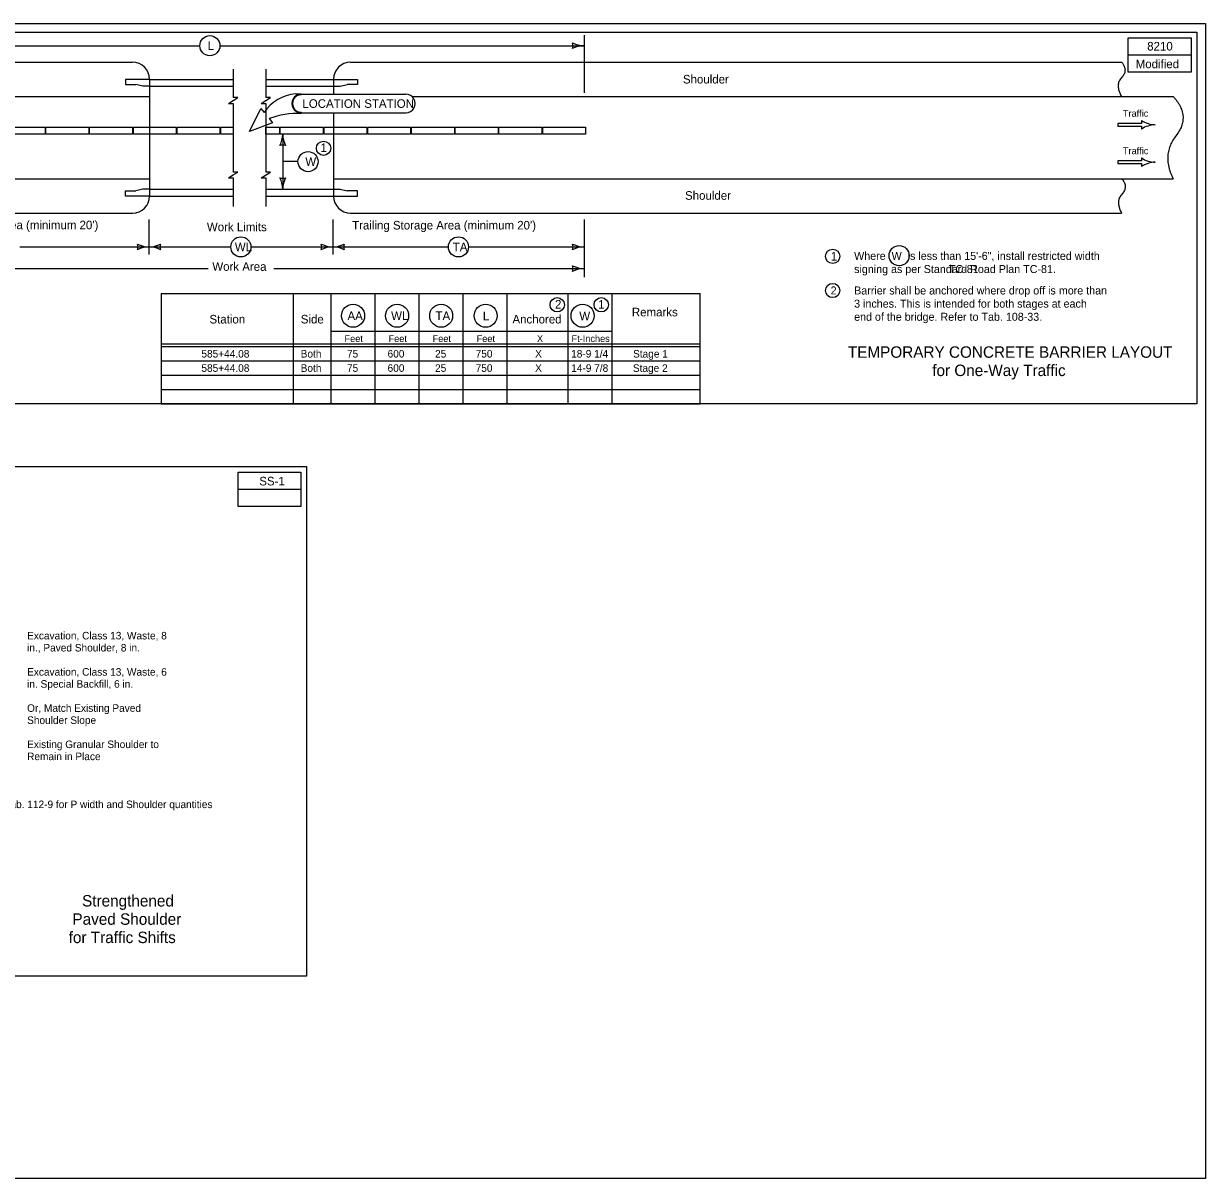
# Model space of a CAD drawing. Extents: x 8045 to 81668, y 6217 to 16762.
# Drawn here: x 14801 to 16868, y 7924 to 9944 of the extents above; entities that cross this region are included whole.
import ezdxf

# ---------------------------------------------------------------- set-up
doc = ezdxf.new("R2010")
doc.units = 0
for name, color, linetype in [('dsnNonPlotable', 7, 'Continuous'), ('dsnShtPlotShapeBatchPrint', 7, 'Continuous'), ('dsnStdBlockModified', 7, 'Continuous'), ('dsnStdBlockNotModified', 7, 'Continuous'), ('dsnStdBorder', 7, 'Continuous'), ('dsnStdLineWork', 7, 'Continuous'), ('dsnStdNameDate', 7, 'Continuous'), ('dsnStdSection', 7, 'Continuous'), ('Level 2', 7, 'Continuous'), ('Level 3', 7, 'Continuous'), ('Level 5', 7, 'Continuous')]:
    doc.layers.add(name, color=color, linetype=linetype)

msp = doc.modelspace()

# ---------------------------------------------------------------- linework, layer by layer
at = {"layer": 'dsnNonPlotable'}
for p, q in [((15781, 9924.1), (15781, 9823.2)), ((14230.5, 9905.4), (15109, 9905.4)), ((15144.3, 9905.4), (15781, 9905.4)), ((13862.8, 9876.4), (14991.3, 9876.4)), ((15167.3, 9864.4), (15167.3, 9814.6)), ((15224.4, 9864.4), (15224.4, 9814.6)), ((15372.7, 9876.4), (16721.1, 9876.4)), ((15021.3, 9846.4), (14979.3, 9846.4)), ((14979.3, 9846.4), (14979.3, 9837.4)), ((14979.3, 9837.4), (14997.3, 9837.4)), ((15009.3, 9834.4), (14997.3, 9837.4)), ((15021.3, 9846.4), (15021.3, 9642.4)), ((15021.3, 9846.4), (15167.3, 9846.4)), ((15224.4, 9846.4), (15342.7, 9846.4)), ((15342.7, 9846.4), (15384.7, 9846.4)), ((15342.7, 9846.4), (15342.7, 9820.5)), ((15354.7, 9834.4), (15366.7, 9837.4)), ((15384.7, 9837.4), (15366.7, 9837.4)), ((15384.7, 9846.4), (15384.7, 9837.4)), ((13779.2, 9816.4), (15021.3, 9816.4)), ((15021.3, 9834.4), (15009.3, 9834.4)), ((15021.3, 9834.4), (15167.3, 9834.4)), ((15224.4, 9834.4), (15342.7, 9834.4)), ((15276.8, 9821), (15286.3, 9821.4)), ((15286.3, 9821.4), (15286.3, 9819.6)), ((15286.3, 9820.5), (15469.4, 9820.5)), ((15342.7, 9834.4), (15354.7, 9834.4)), ((15480.2, 9816.4), (16811.5, 9816.4)), ((15159.3, 9804.5), (15167.3, 9809.5)), ((15159.3, 9804.5), (15167.3, 9804.5)), ((15167.3, 9809.5), (15175.3, 9814.6)), ((15175.3, 9814.6), (15167.3, 9814.6)), ((15167.3, 9804.5), (15167.3, 9744.4)), ((15216.4, 9804.5), (15232.4, 9814.6)), ((15216.4, 9804.5), (15224.4, 9804.5)), ((15232.4, 9814.6), (15224.4, 9814.6)), ((15224.4, 9804.5), (15224.4, 9744.4)), ((15195.9, 9755.5), (15216, 9795.5)), ((15216, 9795.5), (15221.6, 9788.4)), ((15230.2, 9777.8), (15236.1, 9770.5)), ((15286.3, 9788.9), (15286.3, 9787.1)), ((15286.3, 9788), (15469.4, 9788)), ((15342.7, 9788), (15342.7, 9642.4)), ((15236.1, 9770.5), (15195.9, 9755.5)), ((16755.8, 9769.3), (16714.6, 9769.3)), ((16714.6, 9769.3), (16714.6, 9764.8)), ((16714.6, 9764.8), (16755.8, 9764.8)), ((16755.8, 9774.5), (16755.8, 9769.3)), ((16755.8, 9764.8), (16755.8, 9759.5)), ((16779.8, 9767), (16779.8, 9767)), ((15167.3, 9744.4), (15167.3, 9684.4)), ((15224.4, 9744.4), (15224.4, 9684.4)), ((15254, 9750.7), (15254, 9654.4)), ((15280.6, 9702.6), (15254, 9702.6)), ((16755.8, 9703.8), (16714.6, 9703.8)), ((16714.6, 9703.8), (16714.6, 9699.3)), ((16714.6, 9699.3), (16755.8, 9699.3)), ((16755.8, 9709.1), (16755.8, 9703.8)), ((16755.8, 9699.3), (16755.8, 9694.1)), ((16779.8, 9701.6), (16779.8, 9701.6)), ((13779.2, 9672.4), (15021.3, 9672.4)), ((15159.3, 9674.3), (15167.3, 9679.3)), ((15159.3, 9674.3), (15167.3, 9674.3)), ((15167.3, 9679.3), (15175.3, 9684.4)), ((15175.3, 9684.4), (15167.3, 9684.4)), ((15167.3, 9674.3), (15167.3, 9624.4)), ((15216.4, 9674.3), (15232.4, 9684.4)), ((15216.4, 9674.3), (15224.4, 9674.3)), ((15232.4, 9684.4), (15224.4, 9684.4)), ((15224.4, 9674.3), (15224.4, 9624.4)), ((15342.7, 9672.4), (16811.5, 9672.4)), ((14979.3, 9651.4), (14997.3, 9651.4)), ((14979.3, 9642.4), (14979.3, 9651.4)), ((15009.3, 9654.4), (14997.3, 9651.4)), ((15021.3, 9654.4), (15009.3, 9654.4)), ((15021.3, 9654.4), (15167.3, 9654.4)), ((15224.4, 9654.4), (15342.7, 9654.4)), ((15342.7, 9654.4), (15354.7, 9654.4)), ((15354.7, 9654.4), (15366.7, 9651.4)), ((15384.7, 9651.4), (15366.7, 9651.4)), ((15384.7, 9642.4), (15384.7, 9651.4)), ((15021.3, 9642.4), (14979.3, 9642.4)), ((15021.3, 9642.4), (15167.3, 9642.4)), ((15224.4, 9642.4), (15342.7, 9642.4)), ((15342.7, 9642.4), (15384.7, 9642.4)), ((13862.8, 9612.4), (14991.3, 9612.4)), ((15372.7, 9612.4), (16721.1, 9612.4)), ((15020.1, 9601.2), (15020.1, 9539.9)), ((15341.5, 9601.2), (15341.5, 9539.9)), ((15781, 9601.2), (15781, 9500.3)), ((14794, 9553.4), (15020.1, 9553.4)), ((15020.1, 9553.4), (15163.3, 9553.4)), ((15198.3, 9553.4), (15341.5, 9553.4)), ((15211, 9553.4), (15341.5, 9553.4)), ((15341.5, 9553.4), (15543.6, 9553.4)), ((15578.9, 9553.4), (15781, 9553.4)), ((14532.6, 9515.5), (15123.4, 9515.5)), ((15238.7, 9515.5), (15781, 9515.5)), ((15240.1, 9515.5), (15341.5, 9515.5)), ((15272.6, 9279), (15272.6, 9472)), ((15338.6, 9279), (15338.6, 9472)), ((15415.6, 9279), (15415.6, 9472)), ((15492.6, 9279), (15492.6, 9472)), ((15569.6, 9279), (15569.6, 9472)), ((15338.6, 9406.2), (15830.1, 9406.2)), ((15041.6, 9384), (15984.1, 9384)), ((15041.6, 9379), (15984.1, 9379))]:
    msp.add_line(p, q, dxfattribs=at)
for points in [[(14763.3, 9762.7), (14838.3, 9762.7), (14838.3, 9750.7), (14763.3, 9750.7)], [(14839.8, 9762.7), (14914.8, 9762.7), (14914.8, 9750.7), (14839.8, 9750.7)], [(14916.3, 9762.7), (14991.3, 9762.7), (14991.3, 9750.7), (14916.3, 9750.7)], [(14992.8, 9762.7), (15067.8, 9762.7), (15067.8, 9750.7), (14992.8, 9750.7)], [(15069.3, 9762.7), (15144.3, 9762.7), (15144.3, 9750.7), (15069.3, 9750.7)], [(15249.7, 9762.7), (15324.7, 9762.7), (15324.7, 9750.7), (15249.7, 9750.7)], [(15326.2, 9762.7), (15401.2, 9762.7), (15401.2, 9750.7), (15326.2, 9750.7)], [(15402.7, 9762.7), (15477.7, 9762.7), (15477.7, 9750.7), (15402.7, 9750.7)], [(15479.2, 9762.7), (15554.2, 9762.7), (15554.2, 9750.7), (15479.2, 9750.7)], [(15555.7, 9762.7), (15630.7, 9762.7), (15630.7, 9750.7), (15555.7, 9750.7)], [(15632.2, 9762.7), (15707.2, 9762.7), (15707.2, 9750.7), (15632.2, 9750.7)], [(15708.7, 9762.7), (15783.7, 9762.7), (15783.7, 9750.7), (15708.7, 9750.7)]]:
    msp.add_lwpolyline(points, close=True, dxfattribs=at)
for points in [[(15167.3, 9750.7), (15145.8, 9750.7), (15145.8, 9762.7), (15167.3, 9762.7)], [(15167.3, 9762.7), (15167.3, 9750.7)], [(15224.4, 9750.7), (15224.4, 9762.7)], [(15224.4, 9762.7), (15248.2, 9762.7), (15248.2, 9750.7), (15224.4, 9750.7)]]:
    msp.add_lwpolyline(points, dxfattribs=at)
for centre, radius in [((15126.6, 9905.4), 17.6), ((15325.4, 9726), 12.5), ((15298.3, 9702.6), 17.6), ((15180.8, 9553.4), 17.6), ((15561.3, 9553.4), 17.6), ((16215.8, 9537), 12.5), ((16215.8, 9537), 12.5), ((16331.9, 9538.1), 17.6), ((16331.9, 9538.1), 17.6), ((15377.1, 9433), 20.1), ((15454.1, 9433), 20.1), ((15531.1, 9433), 20.1), ((15608.9, 9433), 20.1), ((15734, 9452.2), 12.5), ((15778.4, 9433), 20.1), ((15811, 9452.2), 12.5)]:
    msp.add_circle(centre, radius, dxfattribs=at)
for centre, radius, start, end in [((15745.4, 9905.4), 16.4, 342.2666, 17.7333), ((15781, 9947.9), 42.5, 241.9275, 270), ((15781, 9862.9), 42.5, 90, 118.0725), ((14991.3, 9846.4), 30, 0, 90), ((15372.7, 9846.4), 30, 90, 180), ((16781.7, 9815.4), 48.4, 237.618, 267.648), ((16781.7, 9718.7), 48.4, 92.352, 122.382), ((15211.5, 9750.7), 42.5, 331.9275, 0), ((15296.5, 9750.7), 42.5, 180, 208.0725), ((15254, 9715.1), 16.4, 72.2666, 107.7334), ((16781.7, 9749.9), 48.4, 237.618, 267.648), ((16781.7, 9653.3), 48.4, 92.352, 122.382), ((15254, 9690.1), 16.4, 252.2666, 287.7334), ((15211.5, 9654.4), 42.5, 0, 28.0725), ((15296.5, 9654.4), 42.5, 151.9275, 180), ((14991.3, 9642.4), 30, 270, 360), ((15372.7, 9642.4), 30, 180, 270), ((14984.5, 9553.4), 16.4, 342.2666, 17.7333), ((15020.1, 9595.9), 42.5, 241.9275, 270), ((15020.1, 9510.9), 42.5, 90, 118.0725), ((15020.1, 9595.9), 42.5, 270, 298.0725), ((15020.1, 9510.9), 42.5, 61.9275, 90), ((15055.8, 9553.4), 16.4, 162.2666, 197.7334), ((15305.9, 9553.4), 16.4, 342.2666, 17.7333), ((15341.5, 9595.9), 42.5, 241.9275, 270), ((15341.5, 9510.9), 42.5, 90, 118.0725), ((15341.5, 9595.9), 42.5, 270, 298.0725), ((15341.5, 9510.9), 42.5, 61.9275, 90), ((15377.1, 9553.4), 16.4, 162.2666, 197.7334), ((15745.4, 9553.4), 16.4, 342.2666, 17.7333), ((15781, 9595.9), 42.5, 241.9275, 270), ((15781, 9510.9), 42.5, 90, 118.0725), ((15745.4, 9515.5), 16.4, 342.2666, 17.7333), ((15781, 9558), 42.5, 241.9275, 270), ((15781, 9473), 42.5, 90, 118.0725)]:
    msp.add_arc(centre, radius, start, end, dxfattribs=at)
for centre, major_axis, start_param, end_param in [((15281.3, 9750.7), (-70.8, 0), 4.776871, 5.71778), ((15286.3, 9804.2), (-16.3, 0), 4.712389, 7.853982), ((15286.3, 9804.2), (15.4, 0), 1.570796, 4.712389), ((15469.4, 9804.2), (16.3, 0), 4.712389, 7.853982), ((15283.5, 9631), (-156.9, 0), 4.694293, 5.059134)]:
    msp.add_ellipse(centre, major_axis=major_axis, ratio=0.995025, start_param=start_param, end_param=end_param, dxfattribs=at)
for points in [[(16721.1, 9876.4), (16732.9, 9862.3), (16709.3, 9837.3), (16720.7, 9816.5)], [(16811.5, 9816.4), (16842.9, 9782), (16789.6, 9714), (16811.5, 9672.4)], [(16721.6, 9672.4), (16733.4, 9658.3), (16709.8, 9633.3), (16721.1, 9612.4)]]:
    msp.add_open_spline(points, degree=2, dxfattribs=at)
at = {"layer": 'dsnShtPlotShapeBatchPrint'}
msp.add_lwpolyline([(16842.5, 9919), (16842.5, 9859), (16732.5, 9859), (16732.5, 9919), (16842.5, 9919), (16842.5, 9889), (16732.5, 9889)], dxfattribs=at)
at = {"layer": 'dsnStdBlockModified'}
for p, q in [((13747.5, 9929), (16852.5, 9929)), ((16852.5, 9929), (16852.5, 9279))]:
    msp.add_line(p, q, dxfattribs=at)
at = {"layer": 'dsnStdBlockNotModified'}
for p, q in [((15041.6, 9354), (15984.1, 9354)), ((15041.6, 9329), (15984.1, 9329)), ((15041.6, 9304), (15984.1, 9304)), ((15041.6, 9279), (15984.1, 9279))]:
    msp.add_line(p, q, dxfattribs=at)
at = {"layer": 'dsnStdBorder'}
msp.add_line((16852.5, 9279), (13747.5, 9279), dxfattribs=at)
at = {"layer": 'dsnStdLineWork'}
msp.add_circle((16215.8, 9477.2), 12.5, dxfattribs=at)
at = {"layer": 'dsnStdNameDate'}
msp.add_lwpolyline([(13745, 9169.2), (15295.8, 9169.2), (15295.8, 8277.8), (13745, 8277.8)], close=True, dxfattribs=at)
msp.add_lwpolyline([(15285.8, 9159.2), (15285.8, 9099.2), (15175.8, 9099.2), (15175.8, 9159.2), (15285.8, 9159.2), (15285.8, 9129.2), (15175.8, 9129.2)], dxfattribs=at)
at = {"layer": 'dsnStdSection'}
msp.add_lwpolyline([(13732.5, 9944), (16867.5, 9944), (16867.5, 7924), (13732.5, 7924)], close=True, dxfattribs=at)
at = {"layer": 'Level 2'}
for p, q in [((16852.5, 9929), (16852.5, 9929)), ((15041.6, 9472), (15041.6, 9279)), ((15041.6, 9472), (15984.1, 9472)), ((15646.6, 9279), (15646.6, 9472)), ((15753.1, 9279), (15753.1, 9472)), ((15830.1, 9279), (15830.1, 9472)), ((15984.1, 9279), (15984.1, 9472))]:
    msp.add_line(p, q, dxfattribs=at)

# ---------------------------------------------------------------- texts
at = {"layer": 'dsnStdLineWork'}
for s, height, p in [('2', 14, (16212.2, 9470.2)), ('Barrier shall be anchored where drop off is more than ', 14, (16253.3, 9470.2)), ('3 inches. This is intended for both stages at each ', 14, (16253.3, 9447.2)), ('end of the bridge. Refer to Tab. 108-33.', 14, (16253.3, 9424.2)), ('585+44.08', 13.2, (15111.8, 9359.9)), ('Both', 13.2, (15285.4, 9359.9)), ('75', 13.2, (15366.4, 9359.9)), ('600', 13.2, (15437.4, 9359.9)), ('25', 13.2, (15520.4, 9359.9)), ('750', 13.2, (15591.4, 9359.9)), ('X', 13.2, (15695.4, 9359.9)), ('18-9 1/4', 13.2, (15758.4, 9359.9)), ('Stage 1', 13.2, (15866.7, 9359.9)), ('TEMPORARY CONCRETE BARRIER LAYOUT', 20, (16242.3, 9359.5)), ('585+44.08', 13.2, (15111.8, 9334.9)), ('Both', 13.2, (15285.4, 9334.9)), ('75', 13.2, (15366.4, 9334.9)), ('600', 13.2, (15437.4, 9334.9)), ('25', 13.2, (15520.4, 9334.9)), ('750', 13.2, (15591.4, 9334.9)), ('X', 13.2, (15695.4, 9334.9)), ('14-9 7/8', 13.2, (15758.5, 9334.9)), ('Stage 2', 13.2, (15866.4, 9334.9)), ('for One-Way Traffic', 20, (16389.9, 9327.5)), ('SS-1', 15, (15213, 9136.2)), ('Excavation, Class 13, Waste, 8 ', 13.2, (14807, 8866.8)), ('in., Paved Shoulder, 8 in.', 13.2, (14807, 8845.7)), ('Excavation, Class 13, Waste, 6 ', 13.2, (14807, 8803.4)), ('in. Special Backfill, 6 in.', 13.2, (14807, 8782.3)), ('Or, Match Existing Paved ', 13.2, (14807, 8740.1)), ('Shoulder Slope', 13.2, (14807, 8719)), ('Existing Granular Shoulder to ', 13.2, (14807, 8676.7)), ('Remain in Place', 13.2, (14807, 8655.6)), ('Refer to Tab. 112-9 for P width and Shoulder quantities', 13.2, (14699.4, 8571.7)), ('Strengthened ', 20, (14903.1, 8399.6)), ('Paved Shoulder', 20, (14886.3, 8367.6)), ('for Traffic Shifts', 20, (14879.7, 8335.6))]:
    msp.add_text(s, height=height, dxfattribs=at).set_placement(p)
at = {"layer": 'Level 3'}
for s, p in [('8210', (16765.8, 9897)), ('Modified', (16745.7, 9866))]:
    msp.add_text(s, height=15, dxfattribs=at).set_placement(p)
at = {"layer": 'Level 5'}
for s, height, p in [('L', 15, (15122.7, 9897.9)), ('Shoulder', 15, (15953.9, 9839.3)), ('LOCATION STATION', 15, (15288.5, 9796.7)), ('Traffic', 12, (16723.3, 9781)), ('1', 15, (15320.1, 9719.5)), ('Traffic', 12, (16723.3, 9715.6)), ('W', 15, (15293.6, 9695.1)), ('Shoulder', 15, (15957.6, 9635.9)), ("Approach Storage Area (minimum 20')", 15, (14589.9, 9584.3)), ('Work Limits', 15, (15121.4, 9580.9)), ("Trailing Storage Area (minimum 20')", 15, (15375.4, 9583.9)), ('WL', 15, (15170.3, 9545.9)), ('TA', 15, (15551.4, 9545.9)), ('Work Area', 15, (15130.9, 9511.6)), ('1', 15, (16212.4, 9529.5)), ('1', 15, (16212.4, 9529.5)), ('Where  W  is less than 15\'-6", install restricted width', 14, (16253.3, 9530.7)), ('Where  W  is less than 15\'-6", install restricted width', 14, (16253.3, 9530.7)), ('signing as per Standard Road Plan TC-81.', 14, (16253.3, 9507.7)), ('signing as per Standard Road Plan TC-81.', 14, (16253.3, 9507.7)), ('                                TC-81', 14, (16252.6, 9507.7)), ('                                TC-81', 14, (16252.6, 9507.7)), ('2', 15, (15730.2, 9445.6)), ('1', 15, (15805.8, 9445.6)), ('Remarks', 15, (15864.6, 9431.9)), ('Station', 15, (15125.9, 9419.5)), ('Side', 15, (15285.6, 9419.5)), ('AA', 15, (15367.3, 9425.5)), ('WL', 15, (15443.6, 9425.5)), ('TA', 15, (15521.2, 9425.5)), ('L', 15, (15604, 9425.1)), ('Anchored', 15, (15655.8, 9419.5)), ('W', 15, (15772.7, 9425.1)), ('Feet', 12, (15362.1, 9387)), ('Feet', 12, (15439.1, 9387)), ('Feet', 12, (15516.1, 9387)), ('Feet', 12, (15593.1, 9387)), ('X', 12, (15698.7, 9387)), ('Ft-Inches', 12, (15759.1, 9387))]:
    msp.add_text(s, height=height, dxfattribs=at).set_placement(p)

doc.saveas('drawing.dxf')
